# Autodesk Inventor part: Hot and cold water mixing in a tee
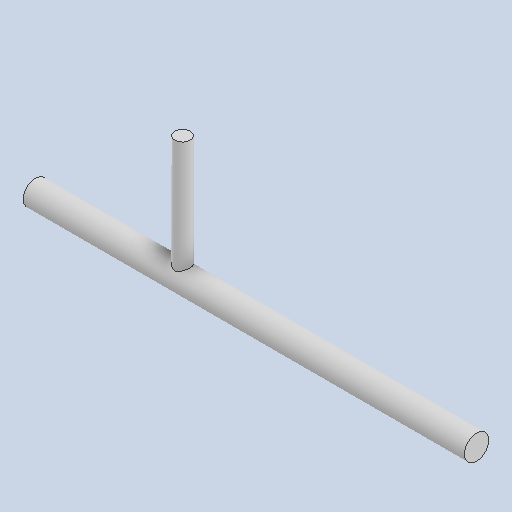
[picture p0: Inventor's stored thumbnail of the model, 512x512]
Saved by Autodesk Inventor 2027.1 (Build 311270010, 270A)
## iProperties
Created: 2026-10
Part Number: Hot and cold water mixing in a tee
Material: Generic
Document SubType Name: Modeling
Designer: niels
Density: 1 g/cm^3
Appearance: Default
Author: niels
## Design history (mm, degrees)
workplane "Work Plane1"
sketch "Sketch1"
  geometry: C1 r 25 at (0, 0)
  constraints: 1 centre point
extrude "Extrusion1" new body sketch "Sketch1" distance "d1" = 900; taper "d2" = 0 deg
workplane "Work Plane2"
sketch "Sketch2"
  geometry: C1 r 16 at (0, 0)
  constraints: 1 centre point
extrude "Extrusion2" join sketch "Sketch2" distance "d4" = 250; taper "d5" = 0 deg
node "Water"
